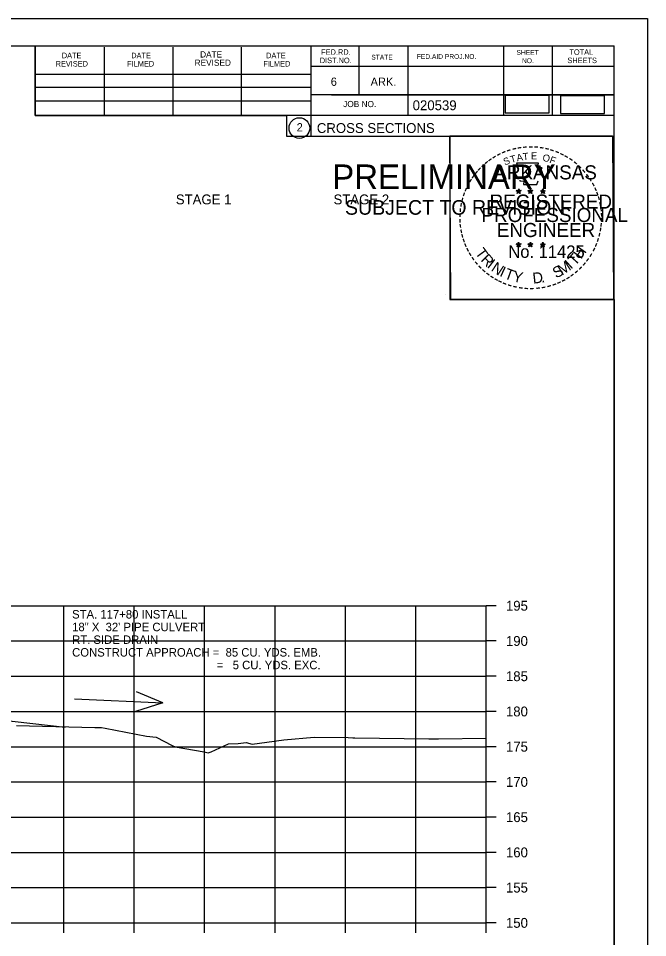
# Model space of a CAD drawing. Extents: x 915787 to 919910, y 133456 to 136717.
# Drawn here: x 916487.5 to 916576.9, y 135459 to 135589.4 of the extents above; entities that cross this region are included whole.
import ezdxf

# ---------------------------------------------------------------- set-up
doc = ezdxf.new("R2010")
doc.units = 0
for name, color, linetype in [('R_Axis', 7, 'Continuous'), ('R_Axis Annot', 7, 'Continuous'), ('R_Border', 7, 'Continuous'), ('R_Border Notes', 7, 'Continuous'), ('R_Border PE', 7, 'Continuous'), ('R_Border Prem', 7, 'Continuous'), ('R_Drive', 7, 'Continuous'), ('R_Exist Surface', 7, 'Continuous'), ('R_Grid', 7, 'Continuous'), ('R_No Plot', 7, 'Continuous'), ('R_Water Annot', 7, 'Continuous'), ('R_Xsect Slope', 7, 'Continuous')]:
    doc.layers.add(name, color=color, linetype=linetype)

msp = doc.modelspace()

# ---------------------------------------------------------------- linework, layer by layer
at = {"layer": 'R_Axis'}
for p, q in [((916553.98, 135461.06), (916553.98, 135506.06)), ((916555.38, 135506.06), (916553.98, 135506.06)), ((916555.38, 135501.06), (916553.98, 135501.06)), ((916555.38, 135496.06), (916553.98, 135496.06)), ((916555.38, 135491.06), (916553.98, 135491.06)), ((916555.38, 135486.06), (916553.98, 135486.06)), ((916555.38, 135481.06), (916553.98, 135481.06)), ((916555.38, 135476.06), (916553.98, 135476.06)), ((916555.38, 135471.06), (916553.98, 135471.06)), ((916555.38, 135466.06), (916553.98, 135466.06)), ((916273.98, 135461.06), (916553.98, 135461.06)), ((916493.98, 135459.66), (916493.98, 135461.06)), ((916503.98, 135459.66), (916503.98, 135461.06)), ((916513.98, 135459.66), (916513.98, 135461.06)), ((916523.98, 135459.66), (916523.98, 135461.06)), ((916533.98, 135459.66), (916533.98, 135461.06)), ((916543.98, 135459.66), (916543.98, 135461.06)), ((916553.98, 135459.66), (916553.98, 135461.06)), ((916555.38, 135461.06), (916553.98, 135461.06))]:
    msp.add_line(p, q, dxfattribs=at)
at = {"layer": 'R_Border'}
for p, q in [((916255.98, 135585.52), (916572.16, 135585.52)), ((916489.9, 135575.64), (916489.9, 135585.52)), ((916499.76, 135575.64), (916499.76, 135585.32)), ((916509.52, 135575.64), (916509.52, 135585.32)), ((916519.2, 135575.64), (916519.2, 135585.32)), ((916529.06, 135585.52), (916529.06, 135572.72)), ((916535.9, 135585.52), (916535.9, 135578.58)), ((916542.84, 135585.52), (916542.84, 135575.64)), ((916556.42, 135585.52), (916556.42, 135575.64)), ((916563.36, 135585.52), (916563.36, 135575.64)), ((916572.16, 135380.06), (916572.16, 135585.52)), ((916572.16, 135582.58), (916529.06, 135582.58)), ((916572.16, 135582.6), (916572.16, 135582.6)), ((916489.9, 135581.5), (916529.06, 135581.5)), ((916489.9, 135579.64), (916529.06, 135579.64)), ((916572.16, 135578.58), (916529.06, 135578.58)), ((916532.02, 135578.58), (916572.16, 135578.58)), ((916489.9, 135575.64), (916489.9, 135577.7)), ((916489.9, 135577.7), (916529.06, 135577.7)), ((916572.16, 135575.64), (916489.9, 135575.64)), ((916529.06, 135572.72), (916572.16, 135572.72))]:
    msp.add_line(p, q, dxfattribs=at)
msp.add_circle((916527.44, 135573.85), 1.47, dxfattribs=at)
at = {"layer": 'R_Border PE'}
for p, q in [((916558.24, 135564.97), (916558.59, 135564.86)), ((916558.24, 135564.97), (916558.49, 135564.93)), ((916558.24, 135564.97), (916558.48, 135564.85)), ((916558.37, 135564.56), (916558.59, 135564.86)), ((916558.37, 135564.56), (916558.5, 135564.81)), ((916558.37, 135564.56), (916558.59, 135564.78)), ((916558.59, 135565.23), (916558.55, 135564.97)), ((916558.59, 135564.86), (916558.59, 135565.23)), ((916558.59, 135565.23), (916558.64, 135564.98)), ((916558.94, 135564.97), (916558.59, 135564.86)), ((916558.8, 135564.56), (916558.59, 135564.86)), ((916558.8, 135564.56), (916558.59, 135564.78)), ((916558.94, 135564.97), (916558.65, 135564.92)), ((916558.8, 135564.56), (916558.66, 135564.85)), ((916558.94, 135564.97), (916558.73, 135564.87)), ((916559.91, 135564.97), (916560.26, 135564.86)), ((916559.91, 135564.97), (916560.16, 135564.93)), ((916559.91, 135564.97), (916560.15, 135564.85)), ((916560.04, 135564.56), (916560.26, 135564.86)), ((916560.04, 135564.56), (916560.17, 135564.81)), ((916560.04, 135564.56), (916560.26, 135564.78)), ((916560.26, 135565.23), (916560.22, 135564.97)), ((916560.26, 135564.86), (916560.26, 135565.23)), ((916560.26, 135565.23), (916560.31, 135564.98)), ((916560.61, 135564.97), (916560.26, 135564.86)), ((916560.47, 135564.56), (916560.26, 135564.86)), ((916560.47, 135564.56), (916560.26, 135564.78)), ((916560.61, 135564.97), (916560.32, 135564.92)), ((916560.47, 135564.56), (916560.33, 135564.85)), ((916560.61, 135564.97), (916560.4, 135564.87)), ((916561.67, 135564.96), (916562.02, 135564.85)), ((916561.67, 135564.96), (916561.93, 135564.91)), ((916561.67, 135564.96), (916561.91, 135564.84)), ((916561.81, 135564.55), (916562.02, 135564.85)), ((916561.81, 135564.55), (916561.93, 135564.8)), ((916561.81, 135564.55), (916562.02, 135564.77)), ((916562.02, 135565.21), (916561.98, 135564.96)), ((916562.02, 135564.85), (916562.02, 135565.21)), ((916562.02, 135565.21), (916562.07, 135564.96)), ((916562.37, 135564.96), (916562.02, 135564.85)), ((916562.24, 135564.55), (916562.02, 135564.85)), ((916562.24, 135564.55), (916562.02, 135564.77)), ((916562.37, 135564.96), (916562.08, 135564.91)), ((916562.24, 135564.55), (916562.1, 135564.84)), ((916562.37, 135564.96), (916562.17, 135564.86)), ((916558.58, 135557.65), (916558.54, 135557.4)), ((916558.58, 135557.29), (916558.58, 135557.65)), ((916558.58, 135557.65), (916558.63, 135557.4)), ((916560.25, 135557.65), (916560.21, 135557.4)), ((916560.25, 135557.29), (916560.25, 135557.65)), ((916560.25, 135557.65), (916560.3, 135557.4)), ((916562.02, 135557.64), (916561.98, 135557.39)), ((916562.02, 135557.28), (916562.02, 135557.64)), ((916562.02, 135557.64), (916562.07, 135557.39)), ((916558.24, 135557.4), (916558.58, 135557.29)), ((916558.24, 135557.4), (916558.49, 135557.35)), ((916558.24, 135557.4), (916558.47, 135557.28)), ((916558.37, 135556.99), (916558.58, 135557.29)), ((916558.37, 135556.99), (916558.49, 135557.23)), ((916558.37, 135556.99), (916558.58, 135557.21)), ((916558.93, 135557.4), (916558.58, 135557.29)), ((916558.8, 135556.99), (916558.58, 135557.29)), ((916558.8, 135556.99), (916558.58, 135557.2)), ((916558.93, 135557.4), (916558.65, 135557.35)), ((916558.8, 135556.99), (916558.66, 135557.28)), ((916558.93, 135557.4), (916558.73, 135557.3)), ((916559.9, 135557.4), (916560.25, 135557.29)), ((916559.9, 135557.4), (916560.16, 135557.35)), ((916559.9, 135557.4), (916560.14, 135557.28)), ((916560.04, 135556.99), (916560.25, 135557.29)), ((916560.04, 135556.99), (916560.16, 135557.23)), ((916560.04, 135556.99), (916560.25, 135557.21)), ((916560.6, 135557.4), (916560.25, 135557.29)), ((916560.47, 135556.99), (916560.25, 135557.29)), ((916560.47, 135556.99), (916560.25, 135557.2)), ((916560.6, 135557.4), (916560.31, 135557.35)), ((916560.47, 135556.99), (916560.33, 135557.28)), ((916560.6, 135557.4), (916560.4, 135557.3)), ((916561.67, 135557.39), (916562.02, 135557.28)), ((916561.67, 135557.39), (916561.92, 135557.34)), ((916561.67, 135557.39), (916561.91, 135557.27)), ((916561.8, 135556.98), (916562.02, 135557.28)), ((916561.8, 135556.98), (916561.93, 135557.22)), ((916561.8, 135556.98), (916562.02, 135557.2)), ((916562.37, 135557.39), (916562.02, 135557.28)), ((916562.23, 135556.98), (916562.02, 135557.28)), ((916562.23, 135556.98), (916562.02, 135557.19)), ((916562.37, 135557.39), (916562.08, 135557.34)), ((916562.23, 135556.98), (916562.1, 135557.27)), ((916562.37, 135557.39), (916562.16, 135557.29))]:
    msp.add_line(p, q, dxfattribs=at)
for points in [[(916558.28, 135568.85), (916558.55, 135568.02)], [(916561.79, 135567.93), (916561.93, 135568.21), (916561.25, 135568.19), (916561.4, 135568.85), (916558.28, 135568.85)], [(916558.77, 135566.43), (916558.77, 135566.34), (916559.34, 135566.32), (916559.28, 135565.85), (916561.15, 135565.85), (916561.35, 135566.38)], [(916558.59, 135565.23), (916558.8, 135564.56), (916558.24, 135564.97), (916558.94, 135564.97), (916558.37, 135564.56), (916558.59, 135565.23)], [(916560.26, 135565.23), (916560.47, 135564.56), (916559.91, 135564.97), (916560.61, 135564.97), (916560.04, 135564.56), (916560.26, 135565.23)], [(916562.02, 135565.21), (916562.24, 135564.55), (916561.67, 135564.96), (916562.37, 135564.96), (916561.81, 135564.55), (916562.02, 135565.21)], [(916558.58, 135557.65), (916558.8, 135556.99), (916558.24, 135557.4), (916558.93, 135557.4), (916558.37, 135556.99), (916558.58, 135557.65)], [(916560.25, 135557.65), (916560.47, 135556.99), (916559.9, 135557.4), (916560.6, 135557.4), (916560.04, 135556.99), (916560.25, 135557.65)], [(916562.02, 135557.64), (916562.23, 135556.98), (916561.67, 135557.39), (916562.37, 135557.39), (916561.8, 135556.98), (916562.02, 135557.64)]]:
    msp.add_lwpolyline(points, dxfattribs=at)
for centre, radius in [((916558.59, 135564.86), 0.172), ((916558.59, 135564.86), 0.145), ((916558.59, 135564.86), 0.116), ((916558.59, 135564.86), 0.0991), ((916558.59, 135564.86), 0.0747), ((916558.59, 135564.86), 0.0495), ((916558.59, 135564.86), 0.0296), ((916560.26, 135564.86), 0.172), ((916560.26, 135564.86), 0.145), ((916560.26, 135564.86), 0.116), ((916560.26, 135564.86), 0.0991), ((916560.26, 135564.86), 0.0747), ((916560.26, 135564.86), 0.0495), ((916560.26, 135564.86), 0.0296), ((916562.02, 135564.85), 0.172), ((916562.02, 135564.85), 0.145), ((916562.02, 135564.85), 0.116), ((916562.02, 135564.85), 0.0991), ((916562.02, 135564.85), 0.0747), ((916562.02, 135564.85), 0.0495), ((916562.02, 135564.85), 0.0296), ((916558.58, 135557.29), 0.172), ((916558.58, 135557.29), 0.145), ((916558.58, 135557.29), 0.116), ((916558.58, 135557.29), 0.0991), ((916558.58, 135557.29), 0.0747), ((916558.58, 135557.29), 0.0495), ((916558.58, 135557.29), 0.0296), ((916560.25, 135557.29), 0.172), ((916560.25, 135557.29), 0.145), ((916560.25, 135557.29), 0.116), ((916560.25, 135557.29), 0.0991), ((916560.25, 135557.29), 0.0747), ((916560.25, 135557.29), 0.0495), ((916560.25, 135557.29), 0.0296), ((916562.02, 135557.28), 0.172), ((916562.02, 135557.28), 0.145), ((916562.02, 135557.28), 0.116), ((916562.02, 135557.28), 0.0991), ((916562.02, 135557.28), 0.0747), ((916562.02, 135557.28), 0.0495), ((916562.02, 135557.28), 0.0296)]:
    msp.add_circle(centre, radius, dxfattribs=at)
at = {"layer": 'R_Drive'}
msp.add_line((916459.92, 135492.7), (916494.19, 135488.81), dxfattribs=at)
at = {"layer": 'R_Exist Surface'}
msp.add_lwpolyline([(916487.25, 135489.05), (916498.38, 135488.8), (916499.34, 135488.79), (916499.84, 135488.67), (916501.34, 135488.42), (916505.71, 135487.57), (916507.11, 135487.42), (916509.38, 135486.25), (916509.81, 135486.04), (916513.91, 135485.32), (916514.49, 135485.2), (916514.89, 135485.34), (916517.35, 135486.45), (916518.74, 135486.53), (916519.87, 135486.65), (916520.74, 135486.42), (916522.82, 135486.69), (916525.21, 135487.03), (916529.52, 135487.41), (916534.38, 135487.35), (916535.03, 135487.32), (916535.3, 135487.34), (916545.83, 135487.18), (916547.18, 135487.16), (916553.98, 135487.25)], dxfattribs=at)
at = {"layer": 'R_Grid'}
for p, q in [((916273.98, 135506.06), (916553.98, 135506.06)), ((916493.98, 135461.06), (916493.98, 135506.06)), ((916503.98, 135461.06), (916503.98, 135506.06)), ((916513.98, 135461.06), (916513.98, 135506.06)), ((916523.98, 135461.06), (916523.98, 135506.06)), ((916533.98, 135461.06), (916533.98, 135506.06)), ((916543.98, 135461.06), (916543.98, 135506.06)), ((916553.98, 135461.06), (916553.98, 135506.06)), ((916273.98, 135501.06), (916553.98, 135501.06)), ((916273.98, 135496.06), (916553.98, 135496.06)), ((916273.98, 135491.06), (916553.98, 135491.06)), ((916273.98, 135486.06), (916553.98, 135486.06)), ((916273.98, 135481.06), (916553.98, 135481.06)), ((916273.98, 135476.06), (916553.98, 135476.06)), ((916273.98, 135471.06), (916553.98, 135471.06)), ((916273.98, 135466.06), (916553.98, 135466.06)), ((916273.98, 135461.06), (916553.98, 135461.06))]:
    msp.add_line(p, q, dxfattribs=at)
at = {"layer": 'R_No Plot'}
for p, q in [((916243.57, 135589.41), (916576.91, 135589.41)), ((916548.19, 135550.26), (916548.19, 135550.26))]:
    msp.add_line(p, q, dxfattribs=at)
for points in [[(916243.57, 135589.41), (916576.91, 135589.41), (916576.91, 135376.07), (916243.57, 135376.07)], [(916489.9, 135585.52), (916489.9, 135575.64), (916525.63, 135575.64), (916525.63, 135572.72), (916548.83, 135572.72), (916548.83, 135549.5), (916572.16, 135549.5), (916572.16, 135380.06), (916255.98, 135380.06), (916255.98, 135585.52)], [(916548.83, 135572.75), (916571.92, 135572.75), (916572.04, 135549.5), (916548.94, 135549.5)]]:
    msp.add_lwpolyline(points, close=True, dxfattribs=at)
at = {"layer": 'R_Water Annot'}
for p, q in [((916508.06, 135492.27), (916504.29, 135493.85)), ((916495.51, 135492.87), (916508.06, 135492.27)), ((916508.06, 135492.27), (916504.15, 135491.06))]:
    msp.add_line(p, q, dxfattribs=at)
at = {"layer": 'R_Xsect Slope'}
for points in [[(916556.68, 135575.99), (916562.93, 135575.99), (916562.93, 135578.47), (916556.68, 135578.47)], [(916564.53, 135575.93), (916570.78, 135575.93), (916570.78, 135578.41), (916564.53, 135578.41)]]:
    msp.add_lwpolyline(points, close=True, dxfattribs=at)

# ---------------------------------------------------------------- texts
at = {"layer": 'R_Axis Annot'}
for s, p in [('195', (916556.78, 135505.36)), ('190', (916556.78, 135500.36)), ('185', (916556.78, 135495.36)), ('180', (916556.78, 135490.36)), ('175', (916556.78, 135485.36)), ('170', (916556.78, 135480.36)), ('165', (916556.78, 135475.36)), ('160', (916556.78, 135470.36)), ('155', (916556.78, 135465.36)), ('150', (916556.78, 135460.36))]:
    msp.add_text(s, height=1.4, dxfattribs=at).set_placement(p)
at = {"layer": 'R_Border'}
for s, height, p in [('DATE', 0.782, (916493.7, 135583.76)), ('DATE', 0.782, (916503.56, 135583.76)), ('DATE', 0.879, (916513.34, 135583.86)), ('DATE', 0.782, (916522.72, 135583.76)), ('DIST.NO.', 0.782, (916530.34, 135583.06)), ('FED.RD.', 0.782, (916530.54, 135584.24)), ('STATE', 0.684, (916537.66, 135583.56)), ('FED.AID PROJ.NO.', 0.684, (916544.12, 135583.66)), ('SHEET', 0.684, (916558.28, 135584.24)), ('NO.', 0.684, (916559.06, 135583.06)), ('SHEETS', 0.782, (916565.52, 135583.06)), ('TOTAL', 0.782, (916565.8, 135584.24)), ('REVISED', 0.782, (916492.82, 135582.58)), ('FILMED', 0.782, (916502.98, 135582.58)), ('REVISED', 0.879, (916512.56, 135582.68)), ('FILMED', 0.782, (916522.32, 135582.58)), ('6', 1.17, (916531.9, 135579.84)), ('ARK.', 1.172, (916537.56, 135579.84)), ('JOB NO.', 0.879, (916533.66, 135576.82)), ('020539', 1.4, (916543.53, 135576.38)), ('2', 1.17, (916527.06, 135573.37)), ('CROSS SECTIONS', 1.4, (916529.92, 135573.15))]:
    msp.add_text(s, height=height, rotation=360, dxfattribs=at).set_placement(p)
at = {"layer": 'R_Border Notes'}
for s, p in [('STAGE 1', (916509.89, 135563.02)), ('STAGE 2', (916532.29, 135563.02))]:
    msp.add_text(s, height=1.4, dxfattribs=at).set_placement(p)
at = {"layer": 'R_Border PE'}
for s, height, rotation, p in [('-', 1.6, 19.1761, (916557.03, 135569.98)), ('-', 1.6, 13.6301, (916557.78, 135570.22)), ('-', 1.6, 10.2193, (916558.46, 135570.38)), ('-', 1.6, 5.8968, (916559.19, 135570.49)), ('-', 1.6, 0.1862, (916559.96, 135570.56)), ('-', 1.6, 357.743, (916560.68, 135570.55)), ('-', 1.6, 352.1617, (916561.42, 135570.49)), ('-', 1.6, 347.2049, (916562.14, 135570.38)), ('-', 1.6, 342.3362, (916562.78, 135570.22)), ('-', 1.6, 36.2317, (916554.59, 135568.63)), ('-', 1.6, 34.0636, (916555.16, 135569.02)), ('-', 1.6, 28.7918, (916555.76, 135569.39)), ('-', 1.6, 24.3072, (916556.39, 135569.71)), ('S', 1, 21.594, (916556.64, 135568.53)), ('T', 1, 16.4036, (916557.55, 135568.86)), ('A', 1, 11.2132, (916558.38, 135569.11)), ('T', 1, 6.0228, (916559.22, 135569.28)), ('E', 1, 0.8323, (916560.33, 135569.39)), ('O', 1, 350.4515, (916561.93, 135569.18)), ('F', 1, 340.0707, (916562.89, 135568.95)), ('-', 1.6, 337.8551, (916563.51, 135570)), ('-', 1.6, 334.1211, (916564.14, 135569.73)), ('-', 1.6, 329.6409, (916564.72, 135569.45)), ('-', 1.6, 325.8627, (916565.37, 135569.09)), ('-', 1.6, 48.423, (916553.23, 135567.35)), ('-', 1.6, 42.9622, (916553.68, 135567.83)), ('-', 1.6, 38.9507, (916554.11, 135568.25)), ('ARKANSAS', 2, 360, (916555.13, 135566.56)), ('-', 1.6, 320.5297, (916565.98, 135568.66)), ('-', 1.6, 315.5786, (916566.58, 135568.17)), ('-', 1.6, 54.2325, (916552.41, 135566.3)), ('-', 1.6, 50.6142, (916552.83, 135566.87)), ('-', 1.6, 309.8797, (916567.14, 135567.62)), ('-', 1.6, 306.6522, (916567.67, 135567.02)), ('-', 1.6, 62.8713, (916551.78, 135565.16)), ('-', 1.6, 58.0706, (916552.09, 135565.77)), ('-', 1.4, 303.6753, (916568.16, 135566.45)), ('-', 1.6, 299.6684, (916568.47, 135565.84)), ('-', 1.6, 72.3945, (916551.3, 135563.92)), ('-', 1.6, 67.7743, (916551.52, 135564.55)), ('REGISTERED', 2, 360, (916554.46, 135562.41)), ('DWB', 0.01, 360, (916558.58, 135564.86)), ('DWB', 0.01, 360, (916560.25, 135564.86)), ('DWB', 0.01, 360, (916562.01, 135564.84)), ('-', 1.6, 294.6628, (916568.8, 135565.23)), ('-', 1.6, 290.5728, (916569.06, 135564.66)), ('-', 1.6, 285.1233, (916569.29, 135564.08)), ('-', 1.6, 81.2013, (916550.97, 135562.49)), ('-', 1.6, 75.461, (916551.1, 135563.2)), ('-', 1.6, 280.5493, (916569.49, 135563.33)), ('-', 1.6, 89.0622, (916550.87, 135561.1)), ('-', 1.6, 85.1863, (916550.89, 135561.8)), ('PROFESSIONAL', 2, 360, (916553.31, 135560.51)), ('-', 1.6, 276.5962, (916569.65, 135562.57)), ('-', 1.6, 274.3301, (916569.71, 135561.84)), ('-', 1.6, 94.1959, (916550.9, 135560.37)), ('ENGINEER', 2, 360, (916555.49, 135558.38)), ('-', 1.6, 263.5172, (916569.73, 135560.55)), ('-', 1.6, 269.9407, (916569.75, 135561.21)), ('-', 1.6, 98.9479, (916550.97, 135559.71)), ('-', 1.6, 101.7149, (916551.11, 135558.97)), ('-', 1.6, 255.7626, (916569.55, 135559.21)), ('-', 1.6, 260.9953, (916569.66, 135559.89)), ('-', 1.6, 105.4578, (916551.27, 135558.38)), ('-', 1.6, 109.0874, (916551.49, 135557.75)), ('-', 1.6, 252.8681, (916569.36, 135558.49)), ('-', 1.6, 114.0643, (916551.74, 135557.15)), ('-', 1.6, 115.7289, (916552.05, 135556.53)), ('T', 1.54, 306.0406, (916552.34, 135556.13)), ('No. 11425', 1.757, 360, (916557.12, 135555.43)), ('DWB', 0.01, 360, (916558.57, 135557.28)), ('DWB', 0.01, 360, (916560.24, 135557.28)), ('DWB', 0.01, 360, (916562.01, 135557.27)), ('H', 1.54, 54.6088, (916567.46, 135555.16)), ('-', 1.6, 244.6197, (916568.88, 135557.19)), ('-', 1.6, 247.8887, (916569.14, 135557.82)), ('-', 1.6, 120.4471, (916552.4, 135555.95)), ('-', 1.6, 125.8934, (916552.81, 135555.39)), ('R', 1.54, 314.005, (916553.11, 135555.08)), ('I', 1.54, 321.9694, (916554.01, 135554.15)), ('I', 1.54, 42.1136, (916566.01, 135553.74)), ('T', 1.54, 46.6444, (916566.58, 135554.22)), ('-', 1.6, 233.8452, (916568.08, 135555.79)), ('-', 1.6, 239.0712, (916568.49, 135556.44)), ('-', 1.6, 130.7181, (916553.27, 135554.83)), ('-', 1.6, 134.2238, (916553.78, 135554.29)), ('-', 1.6, 138.9338, (916554.31, 135553.83)), ('N', 1.54, 326.5002, (916554.57, 135553.67)), ('I', 1.54, 335.3603, (916555.78, 135552.89)), ('T', 1.54, 339.8912, (916556.44, 135552.56)), ('S', 1.54, 26.9312, (916563.89, 135552.49)), ('M', 1.54, 32.6563, (916564.73, 135552.89)), ('-', 1.6, 225.7653, (916567.17, 135554.66)), ('-', 1.6, 231.2538, (916567.65, 135555.22)), ('-', 1.6, 144.6463, (916554.87, 135553.42)), ('-', 1.6, 148.0898, (916555.43, 135553.05)), ('-', 1.6, 151.5704, (916556.01, 135552.72)), ('Y', 1.54, 347.8556, (916557.66, 135552.12)), ('D', 1.54, 6.3969, (916560.65, 135551.76)), ('-', 1.6, 207.3568, (916565.01, 135552.94)), ('-', 1.6, 212.2491, (916565.57, 135553.29)), ('-', 1.6, 215.7363, (916566.1, 135553.68)), ('-', 1.6, 221.0851, (916566.65, 135554.15)), ('-', 1.6, 154.6002, (916556.53, 135552.48)), ('-', 1.6, 158.5612, (916557.15, 135552.22)), ('-', 1.6, 162.7983, (916557.84, 135552.01)), ('-', 1.6, 167.5555, (916558.55, 135551.85)), ('-', 1.6, 173.1155, (916559.33, 135551.74)), ('-', 1.6, 176.5183, (916560.07, 135551.68)), ('-', 1.6, 181.5918, (916560.82, 135551.7)), ('-', 1.6, 185.8167, (916561.63, 135551.78)), ('-', 1.6, 191.2858, (916562.36, 135551.91)), ('.', 1.54, 13.7642, (916561.84, 135551.88)), ('-', 1.6, 195.4743, (916563.09, 135552.11)), ('-', 1.6, 200.7184, (916563.77, 135552.35)), ('-', 1.6, 204.2516, (916564.39, 135552.62))]:
    msp.add_text(s, height=height, rotation=rotation, dxfattribs=at).set_placement(p)
at = {"layer": 'R_Border Prem'}
for s, height, p in [('PRELIMINARY', 3.5, (916532.11, 135565.18)), ('DWB', 0.01, (916532.85, 135567.03)), ('SUBJECT TO REVISION', 2.0751, (916533.92, 135561.55))]:
    msp.add_text(s, height=height, rotation=360, dxfattribs=at).set_placement(p)
at = {"layer": 'R_Water Annot'}
for s, p in [('STA. 117+80 INSTALL', (916495.16, 135504.25)), ('18" X  32\' PIPE CULVERT', (916495.16, 135502.45)), ('RT. SIDE DRAIN', (916495.16, 135500.65)), ('CONSTRUCT APPROACH =  85 CU. YDS. EMB.', (916495.16, 135498.85)), ('   =   5 CU. YDS. EXC.', (916514.36, 135497.05))]:
    msp.add_text(s, height=1.2, dxfattribs=at).set_placement(p)

doc.saveas('drawing.dxf')
